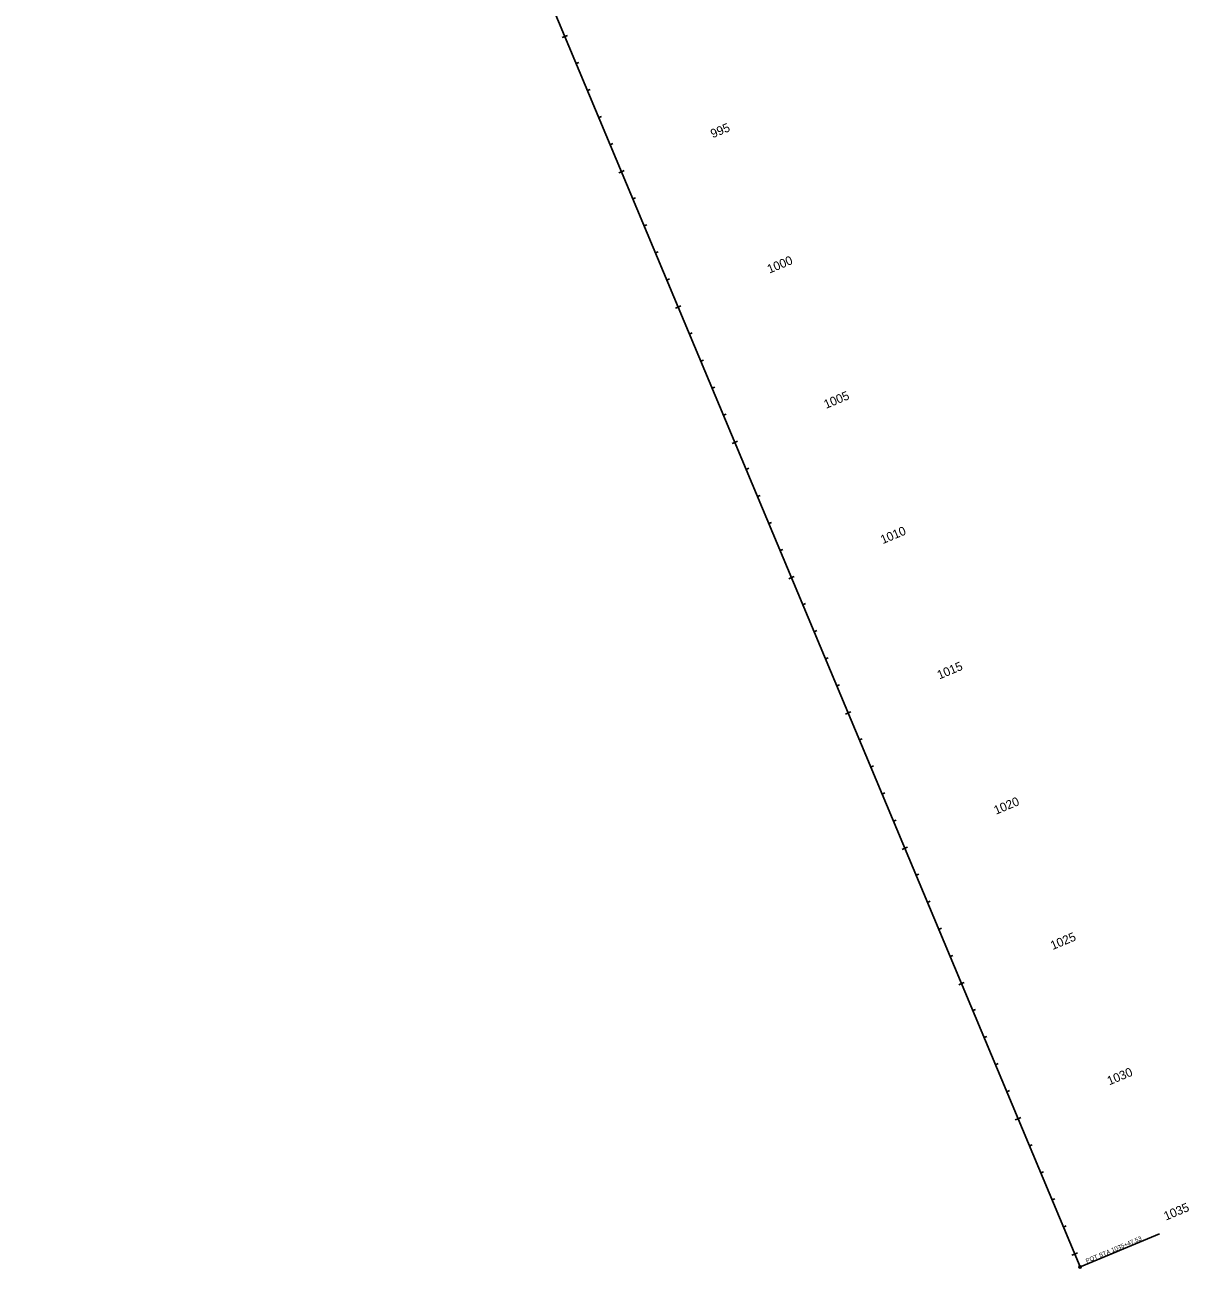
# Model space of a CAD drawing. Extents: x 2819977 to 2827606, y 116785 to 150320.
# Drawn here: x 2821726 to 2825694, y 116785 to 121023 of the extents above; entities that cross this region are included whole.
import ezdxf

# ---------------------------------------------------------------- set-up
doc = ezdxf.new("R2010")
doc.units = 0
doc.layers.add('Roadway-Centerline main', color=7, linetype='Continuous')
doc.layers.add('Roadway-Curve pc pt', color=7, linetype='Continuous')

msp = doc.modelspace()

# ---------------------------------------------------------------- linework, layer by layer
at = {"layer": 'Roadway-Centerline main'}
for p, q in [((2821725.8, 125379.3), (2825322, 116789)), ((2823565.9, 120983.8), (2823556.7, 120979.9)), ((2823565.9, 120983.8), (2823575.1, 120987.7)), ((2823604.5, 120891.6), (2823613.8, 120895.4)), ((2823643.1, 120799.3), (2823652.4, 120803.2)), ((2823681.8, 120707.1), (2823691, 120710.9)), ((2823720.4, 120614.8), (2823729.6, 120618.7)), ((2823759, 120522.6), (2823749.8, 120518.7)), ((2823759, 120522.6), (2823768.2, 120526.5)), ((2823797.6, 120430.4), (2823806.8, 120434.2)), ((2823836.2, 120338.1), (2823845.5, 120342)), ((2823874.8, 120245.9), (2823884.1, 120249.7)), ((2823913.5, 120153.6), (2823922.7, 120157.5)), ((2823952.1, 120061.4), (2823942.9, 120057.5)), ((2823952.1, 120061.4), (2823961.3, 120065.2)), ((2823990.7, 119969.1), (2823999.9, 119973)), ((2824029.3, 119876.9), (2824038.5, 119880.8)), ((2824067.9, 119784.7), (2824077.2, 119788.5)), ((2824106.5, 119692.4), (2824115.8, 119696.3)), ((2824145.2, 119600.2), (2824135.9, 119596.3)), ((2824145.2, 119600.2), (2824154.4, 119604)), ((2824183.8, 119507.9), (2824193, 119511.8)), ((2824222.4, 119415.7), (2824231.6, 119419.5)), ((2824261, 119323.4), (2824270.2, 119327.3)), ((2824299.6, 119231.2), (2824308.9, 119235.1)), ((2824338.3, 119139), (2824347.5, 119142.8)), ((2824338.3, 119139), (2824329, 119135.1)), ((2824376.9, 119046.7), (2824386.1, 119050.6)), ((2824415.5, 118954.5), (2824424.7, 118958.3)), ((2824454.1, 118862.2), (2824463.3, 118866.1)), ((2824492.7, 118770), (2824501.9, 118773.8)), ((2824531.3, 118677.7), (2824522.1, 118673.9)), ((2824531.3, 118677.7), (2824540.6, 118681.6)), ((2824570, 118585.5), (2824579.2, 118589.4)), ((2824608.6, 118493.3), (2824617.8, 118497.1)), ((2824647.2, 118401), (2824656.4, 118404.9)), ((2824685.8, 118308.8), (2824695, 118312.6)), ((2824724.4, 118216.5), (2824715.2, 118212.7)), ((2824724.4, 118216.5), (2824733.6, 118220.4)), ((2824763, 118124.3), (2824772.3, 118128.1)), ((2824801.7, 118032), (2824810.9, 118035.9)), ((2824840.3, 117939.8), (2824849.5, 117943.7)), ((2824878.9, 117847.6), (2824888.1, 117851.4)), ((2824917.5, 117755.3), (2824908.3, 117751.4)), ((2824917.5, 117755.3), (2824926.7, 117759.2)), ((2824956.1, 117663.1), (2824965.3, 117666.9)), ((2824994.7, 117570.8), (2825004, 117574.7)), ((2825033.4, 117478.6), (2825042.6, 117482.4)), ((2825072, 117386.3), (2825081.2, 117390.2)), ((2825110.6, 117294.1), (2825101.4, 117290.2)), ((2825110.6, 117294.1), (2825119.8, 117298)), ((2825149.2, 117201.9), (2825158.4, 117205.7)), ((2825187.8, 117109.6), (2825197, 117113.5)), ((2825226.4, 117017.4), (2825235.7, 117021.2)), ((2825265.1, 116925.1), (2825274.3, 116929)), ((2825303.7, 116832.9), (2825294.4, 116829)), ((2825303.7, 116832.9), (2825312.9, 116836.7))]:
    msp.add_line(p, q, dxfattribs=at)
at = {"layer": 'Roadway-Curve pc pt'}
msp.add_line((2825325.7, 116790.6), (2825593, 116902.5), dxfattribs=at)
msp.add_circle((2825322, 116789), 4, dxfattribs=at)

# ---------------------------------------------------------------- texts
at = {"layer": 'Roadway-Centerline main'}
for s, p in [(' 995', (2824060, 120632.3)), (' 1000', (2824253.1, 120171.1)), (' 1005', (2824446.1, 119709.9)), (' 1010', (2824639.2, 119248.7)), (' 1015', (2824832.3, 118787.5)), (' 1020', (2825025.4, 118326.3)), (' 1025', (2825218.5, 117865)), (' 1030', (2825411.6, 117403.8)), (' 1035', (2825604.6, 116942.6))]:
    msp.add_text(s, height=30, rotation=22.7163, dxfattribs=at).set_placement(p)
at = {"layer": 'Roadway-Curve pc pt'}
msp.add_text('POT STA 1035+47.53', height=15, rotation=22.7163, dxfattribs=at).set_placement((2825344.9, 116801.8))

doc.saveas('drawing.dxf')
